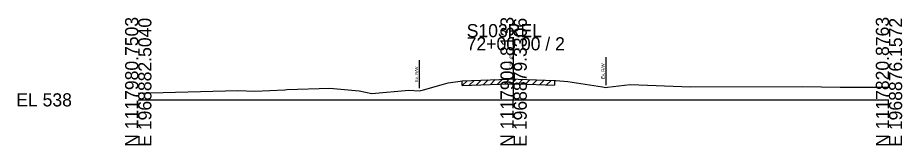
# Model space of a CAD drawing. Extents: x -26 to 163, y -10 to 24518.
# Drawn here: x -25.7 to 162.8, y 20490.3 to 20517.5 of the extents above; entities that cross this region are included whole.
import ezdxf

# ---------------------------------------------------------------- set-up
doc = ezdxf.new("R2010")
doc.units = 0
for name, color, linetype in [('RD_GPK_XS_Cell', 7, 'Continuous'), ('RD_XS_ExGround', 7, 'Continuous'), ('RD_XS_ExPaveRet', 7, 'Continuous'), ('RD_XS_ExRW', 7, 'Continuous'), ('RD_XS_TX_Elev_EX', 7, 'Continuous')]:
    doc.layers.add(name, color=color, linetype=linetype)

msp = doc.modelspace()

# ---------------------------------------------------------------- linework, layer by layer
at = {"layer": 'RD_GPK_XS_Cell'}
for p, q in [((80, 20500), (80, 20513.36)), ((0, 20500), (80, 20500)), ((80, 20500), (160, 20500))]:
    msp.add_line(p, q, dxfattribs=at)
at = {"layer": 'RD_XS_ExGround'}
msp.add_lwpolyline([(0, 20501.44), (21.21, 20502.03), (24.86, 20501.84), (31.25, 20502.17), (31.64, 20502.19), (40.81, 20502.5), (47.07, 20501.92), (49.76, 20501.37), (57.64, 20502.1), (59.9, 20501.96), (60.82, 20502.17), (64.54, 20503.2), (66.07, 20503.62), (68.61, 20503.99), (69.04, 20504.05), (78.98, 20504.41), (80.11, 20504.45), (80.97, 20504.42), (88.68, 20504.12), (88.98, 20504.11), (91.57, 20503.95), (98.95, 20502.75), (99.63, 20502.63), (100.04, 20502.69), (104.84, 20503.3), (117.69, 20502.78), (141.63, 20502.83), (149.6, 20502.73), (160, 20502.69)], dxfattribs=at)
at = {"layer": 'RD_XS_ExPaveRet'}
for p, q in [((69.04, 20503.05), (70.08, 20504.08)), ((69.04, 20503.05), (69.04, 20504.05)), ((69.04, 20503.05), (78.98, 20503.41)), ((70.54, 20503.1), (71.58, 20504.14)), ((72.04, 20503.16), (73.08, 20504.2)), ((73.54, 20503.21), (74.58, 20504.25)), ((75.04, 20503.27), (76.08, 20504.31)), ((76.54, 20503.32), (77.58, 20504.36)), ((78.04, 20503.38), (79.08, 20504.42)), ((78.98, 20503.41), (80.11, 20503.45)), ((79.54, 20503.43), (80.54, 20504.44)), ((80.11, 20503.45), (80.97, 20503.42)), ((80.97, 20503.42), (88.68, 20503.12)), ((81.04, 20503.42), (82, 20504.38)), ((82.54, 20503.36), (83.5, 20504.32)), ((84.04, 20503.3), (85, 20504.27)), ((85.54, 20503.24), (86.5, 20504.21)), ((87.04, 20503.19), (88, 20504.15)), ((88.68, 20504.12), (88.68, 20503.12))]:
    msp.add_line(p, q, dxfattribs=at)
at = {"layer": 'RD_XS_ExRW'}
for p, q in [((99.63, 20509.13), (99.63, 20503.13)), ((59.9, 20508.46), (59.9, 20502.46))]:
    msp.add_line(p, q, dxfattribs=at)

# ---------------------------------------------------------------- texts
at = {"layer": 'RD_GPK_XS_Cell'}
for s, p in [('N 1117980.7503', (0, 20490)), ('E 1968882.5040', (2.8, 20490)), ('N 1117900.8133', (80, 20490)), ('E 1968879.3306', (82.8, 20490)), ('N 1117820.8763', (160, 20490)), ('E 1968876.1572', (162.8, 20490))]:
    msp.add_text(s, height=2.8, rotation=90, dxfattribs=at).set_placement(p)
for s, p in [('S103REL', (70, 20513.36)), ('72+00.00 / 2', (70, 20510.56)), ('EL 538', (-26, 20498.6))]:
    msp.add_text(s, height=2.8, dxfattribs=at).set_placement(p)
at = {"layer": 'RD_XS_ExRW'}
for p in [(59.65, 20503.8), (99.38, 20504.48)]:
    msp.add_text('Ex. R/W ', height=0.65, rotation=90, dxfattribs=at).set_placement(p)
at = {"layer": 'RD_XS_TX_Elev_EX'}
msp.add_text('542.45', height=0.8, rotation=90, dxfattribs=at).set_placement((79.9, 20506.45))

doc.saveas('drawing.dxf')
